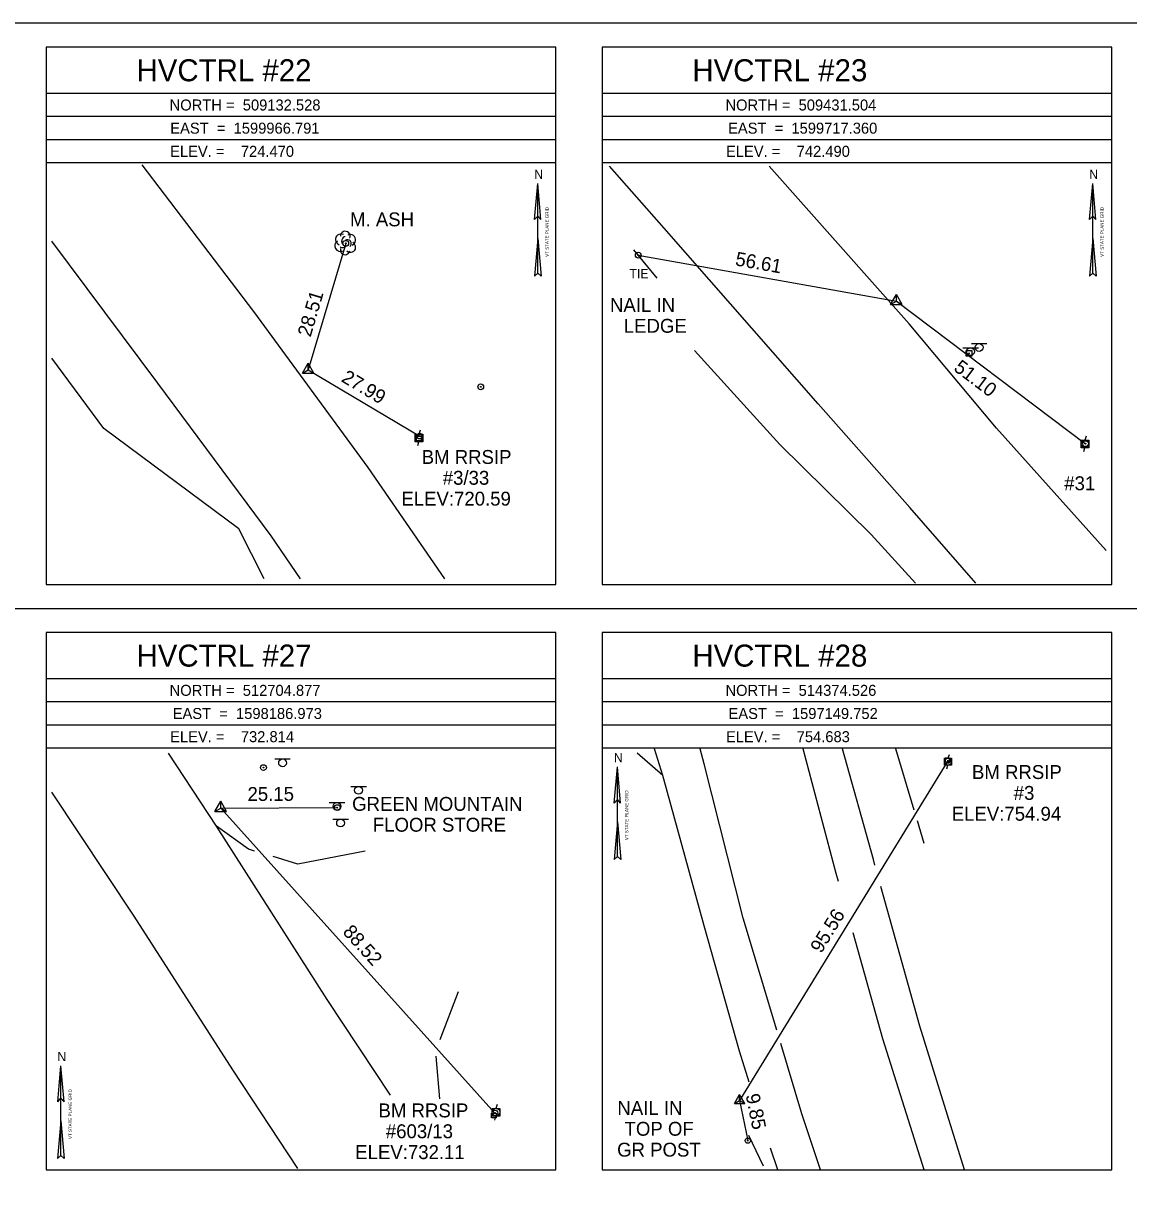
# Model space of a CAD drawing. Extents: x 1598730 to 1599370, y 501440 to 502728.
# Drawn here: x 1598999.5 to 1599238.2, y 501610.1 to 501860.2 of the extents above; entities that cross this region are included whole.
import ezdxf

# ---------------------------------------------------------------- set-up
doc = ezdxf.new("R2010")
doc.units = 0
for name, color, linetype in [('C_A', 7, 'Continuous'), ('C_C', 7, 'Continuous'), ('CBP', 7, 'Continuous'), ('CPBM', 7, 'Continuous'), ('CPSM', 7, 'Continuous'), ('Default', 7, 'Continuous'), ('L_C', 7, 'Continuous'), ('LARO', 7, 'Continuous'), ('LAWA', 7, 'Continuous'), ('LFNC', 7, 'Continuous'), ('LPST', 7, 'Continuous'), ('LTD', 7, 'Continuous'), ('NBL1', 7, 'Continuous'), ('NBL2', 7, 'Continuous'), ('NNA_P', 7, 'Continuous'), ('PET', 7, 'Continuous'), ('PSP', 7, 'Continuous'), ('RGR', 7, 'Continuous'), ('S_C', 7, 'Continuous'), ('SRM', 7, 'Continuous'), ('SSGN', 7, 'Continuous'), ('U_C', 7, 'Continuous'), ('UP', 7, 'Continuous'), ('UPGW', 7, 'Continuous')]:
    doc.layers.add(name, color=color, linetype=linetype)

msp = doc.modelspace()

# ---------------------------------------------------------------- linework, layer by layer
at = {"layer": 'CBP'}
for centre, radius in [((1599069.18, 501812.68), 0.625), ((1599069.18, 501812.68), 0.0833), ((1599132.32, 501810.14), 0.625), ((1599132.32, 501810.14), 0.0833), ((1599085.15, 501771.09), 0.625), ((1599085.15, 501771.09), 0.0833), ((1599228.87, 501769.44), 0.625), ((1599228.87, 501769.44), 0.0833), ((1599199.19, 501701.02), 0.562), ((1599199.19, 501701.02), 0.075), ((1599067.35, 501690.89), 0.625), ((1599067.35, 501690.89), 0.0833), ((1599101.38, 501624.98), 0.625), ((1599101.38, 501624.98), 0.0833), ((1599155.96, 501619.01), 0.562), ((1599155.96, 501619.01), 0.075)]:
    msp.add_circle(centre, radius, dxfattribs=at)
at = {"layer": 'CPBM'}
for p, q in [((1599084.43, 501770.06), (1599084.43, 501771.06)), ((1599084.43, 501771.06), (1599085.43, 501771.06)), ((1599085.43, 501770.06), (1599084.43, 501770.06)), ((1599084.93, 501770.56), (1599084.93, 501770.56)), ((1599084.93, 501770.56), (1599084.93, 501770.56)), ((1599085.43, 501771.06), (1599085.43, 501770.06)), ((1599198.55, 501700.72), (1599198.55, 501701.62)), ((1599198.55, 501701.62), (1599199.45, 501701.62)), ((1599199.45, 501700.72), (1599198.55, 501700.72)), ((1599199, 501701.17), (1599199, 501701.17)), ((1599199, 501701.17), (1599199, 501701.17)), ((1599199.45, 501701.62), (1599199.45, 501700.72)), ((1599100.64, 501623.96), (1599100.64, 501624.96)), ((1599100.64, 501624.96), (1599101.64, 501624.96)), ((1599101.64, 501624.96), (1599101.64, 501623.96)), ((1599101.64, 501623.96), (1599100.64, 501623.96)), ((1599101.15, 501624.46), (1599101.15, 501624.46)), ((1599101.15, 501624.46), (1599101.15, 501624.46))]:
    msp.add_line(p, q, dxfattribs=at)
at = {"layer": 'CPSM'}
for p, q in [((1599186.8, 501799.47), (1599188.05, 501801.64)), ((1599186.8, 501799.47), (1599188.05, 501800.19)), ((1599189.3, 501799.47), (1599188.05, 501801.64)), ((1599188.05, 501800.19), (1599188.05, 501801.64)), ((1599188.05, 501800.19), (1599188.05, 501800.19)), ((1599188.05, 501800.19), (1599189.3, 501799.47)), ((1599186.8, 501799.47), (1599189.3, 501799.47)), ((1599059.82, 501784.64), (1599061.07, 501786.8)), ((1599059.82, 501784.64), (1599061.07, 501785.36)), ((1599062.32, 501784.64), (1599061.07, 501786.8)), ((1599061.07, 501785.36), (1599061.07, 501786.8)), ((1599061.07, 501785.36), (1599061.07, 501785.36)), ((1599061.07, 501785.36), (1599062.32, 501784.64)), ((1599059.82, 501784.64), (1599062.32, 501784.64)), ((1599040.94, 501690.09), (1599042.19, 501692.26)), ((1599043.44, 501690.09), (1599042.19, 501692.26)), ((1599042.19, 501690.81), (1599042.19, 501692.26)), ((1599040.94, 501690.09), (1599042.19, 501690.81)), ((1599040.94, 501690.09), (1599043.44, 501690.09)), ((1599042.19, 501690.81), (1599042.19, 501690.81)), ((1599042.19, 501690.81), (1599043.44, 501690.09)), ((1599153.08, 501627.05), (1599154.2, 501629)), ((1599153.08, 501627.05), (1599154.21, 501627.7)), ((1599155.33, 501627.05), (1599154.2, 501629)), ((1599154.21, 501627.7), (1599154.2, 501629)), ((1599154.21, 501627.7), (1599154.21, 501627.7)), ((1599154.21, 501627.7), (1599155.33, 501627.05)), ((1599153.08, 501627.05), (1599155.33, 501627.05))]:
    msp.add_line(p, q, dxfattribs=at)
at = {"layer": 'Default'}
for p, q in [((1599069.18, 501812.68), (1599061.07, 501785.36)), ((1599132.32, 501810.14), (1599188.05, 501800.19)), ((1599188.05, 501800.19), (1599228.87, 501769.44)), ((1599061.07, 501785.36), (1599085.15, 501771.09)), ((1599199.19, 501701.02), (1599154.21, 501627.7)), ((1599042.19, 501690.81), (1599067.35, 501690.89)), ((1599101.38, 501624.98), (1599042.19, 501690.81)), ((1599154.21, 501627.7), (1599155.96, 501619.01))]:
    msp.add_line(p, q, dxfattribs=at)
at = {"layer": 'LARO'}
msp.add_lwpolyline([(1599136.42, 501805.14), (1599131.36, 501811.29)], dxfattribs=at)
at = {"layer": 'LAWA'}
for points in [[(1599051.53, 501740.25), (1599046.12, 501751.05), (1599016.95, 501772.73), (1599005.75, 501787.89)], [(1599192.15, 501739.35), (1599182.61, 501749.84), (1599162.87, 501769.29), (1599144.5, 501789.54)]]:
    msp.add_lwpolyline(points, dxfattribs=at)
at = {"layer": 'LFNC'}
for points in [[(1599191.9, 501690.35), (1599187.9, 501703.59)], [(1599194.08, 501683.14), (1599192.59, 501688.06)]]:
    msp.add_lwpolyline(points, dxfattribs=at)
at = {"layer": 'LPST'}
for radius in [0.625, 0.0833]:
    msp.add_circle((1599051.41, 501699.53), radius, dxfattribs=at)
at = {"layer": 'LTD'}
msp.add_line((1599069.04, 501812.82), (1599069.04, 501812.82), dxfattribs=at)
msp.add_line((1599069.04, 501812.82), (1599069.04, 501812.82), dxfattribs=at)
msp.add_arc((1599069.08, 501814.25), 1.05, 335.5272, 180.9563, dxfattribs=at)
for centre, major_axis, ratio, start_param, end_param in [((1599068.24, 501813.48), (1.21, -0.51), 0.895232, 1.570796, 4.712389), ((1599070.08, 501813.4), (-1.14, -0.48), 0.949671, 1.570796, 4.712389), ((1599067.95, 501812.11), (0.58, -1.04), 0.959034, 3.141593, 6.283185), ((1599068.83, 501813.28), (-0.208, -0.792), 0.645439, 3.141593, 6.283185), ((1599069.54, 501812.65), (-0.5, 0.667), 0.989748, 3.141593, 6.283185), ((1599070.04, 501811.98), (-1.09, 0.79), 0.841452, 1.570796, 4.712389), ((1599069.04, 501811.32), (0.26, 1.06), 0.942809, 1.570796, 4.712389), ((1599068.58, 501812.07), (-0.625, -0.083), 0.423636, 0, 3.141593)]:
    msp.add_ellipse(centre, major_axis=major_axis, ratio=ratio, start_param=start_param, end_param=end_param, dxfattribs=at)
at = {"layer": 'NBL1'}
msp.add_lwpolyline([(1598729.53, 501440.21), (1599369.53, 501440.21), (1599369.53, 501860.21), (1598729.53, 501860.21)], close=True, dxfattribs=at)
at = {"layer": 'NBL2'}
for p, q in [((1599114.53, 501845.04), (1599004.53, 501845.04)), ((1599234.53, 501845.04), (1599124.53, 501845.04)), ((1599114.53, 501840.04), (1599004.53, 501840.04)), ((1599234.53, 501840.04), (1599124.53, 501840.04)), ((1599114.53, 501835.04), (1599004.53, 501835.04)), ((1599234.53, 501835.04), (1599124.53, 501835.04)), ((1599114.53, 501830.04), (1599004.53, 501830.04)), ((1599234.53, 501830.04), (1599124.53, 501830.04)), ((1598729.53, 501733.88), (1599369.53, 501733.88)), ((1599114.53, 501718.71), (1599004.53, 501718.71)), ((1599234.53, 501718.71), (1599124.53, 501718.71)), ((1599114.53, 501713.71), (1599004.53, 501713.71)), ((1599234.53, 501713.71), (1599124.53, 501713.71)), ((1599114.53, 501708.71), (1599004.53, 501708.71)), ((1599234.53, 501708.71), (1599124.53, 501708.71)), ((1599114.53, 501703.71), (1599004.53, 501703.71)), ((1599234.53, 501703.71), (1599124.53, 501703.71))]:
    msp.add_line(p, q, dxfattribs=at)
for points in [[(1599004.53, 501739.04), (1599114.53, 501739.04), (1599114.53, 501855.04), (1599004.53, 501855.04)], [(1599124.53, 501739.04), (1599234.53, 501739.04), (1599234.53, 501855.04), (1599124.53, 501855.04)], [(1599004.53, 501612.71), (1599114.53, 501612.71), (1599114.53, 501728.71), (1599004.53, 501728.71)], [(1599124.53, 501612.71), (1599234.53, 501612.71), (1599234.53, 501728.71), (1599124.53, 501728.71)]]:
    msp.add_lwpolyline(points, close=True, dxfattribs=at)
at = {"layer": 'NNA_P'}
for p, q in [((1599109.93, 501817.8), (1599110.63, 501825.6)), ((1599110.63, 501806.22), (1599110.63, 501825.6)), ((1599111.32, 501817.8), (1599110.63, 501825.6)), ((1599229.75, 501817.8), (1599230.45, 501825.6)), ((1599230.45, 501806.22), (1599230.45, 501825.6)), ((1599231.14, 501817.8), (1599230.45, 501825.6)), ((1599109.93, 501817.8), (1599110.63, 501818.57)), ((1599111.32, 501817.8), (1599110.63, 501818.57)), ((1599229.75, 501817.8), (1599230.45, 501818.57)), ((1599231.14, 501817.8), (1599230.45, 501818.57)), ((1599110.63, 501813.75), (1599109.91, 501805.58)), ((1599110.63, 501813.75), (1599111.35, 501805.58)), ((1599230.45, 501813.75), (1599229.73, 501805.58)), ((1599230.45, 501813.75), (1599231.17, 501805.58)), ((1599110.63, 501806.22), (1599109.91, 501805.58)), ((1599110.63, 501806.22), (1599111.35, 501805.58)), ((1599230.45, 501806.22), (1599229.73, 501805.58)), ((1599230.45, 501806.22), (1599231.17, 501805.58)), ((1599127.12, 501691.89), (1599127.82, 501699.68)), ((1599127.82, 501680.31), (1599127.82, 501699.68)), ((1599128.51, 501691.89), (1599127.82, 501699.68)), ((1599127.12, 501691.89), (1599127.82, 501692.66)), ((1599128.51, 501691.89), (1599127.82, 501692.66)), ((1599127.82, 501687.84), (1599127.1, 501679.67)), ((1599127.82, 501687.84), (1599128.54, 501679.67)), ((1599127.82, 501680.31), (1599127.1, 501679.67)), ((1599127.82, 501680.31), (1599128.54, 501679.67)), ((1599006.99, 501627.38), (1599007.69, 501635.17)), ((1599007.69, 501615.8), (1599007.69, 501635.17)), ((1599008.38, 501627.38), (1599007.69, 501635.17)), ((1599006.99, 501627.38), (1599007.69, 501628.15)), ((1599008.38, 501627.38), (1599007.69, 501628.15)), ((1599007.69, 501623.32), (1599006.97, 501615.16)), ((1599007.69, 501623.32), (1599008.41, 501615.16)), ((1599007.69, 501615.8), (1599006.97, 501615.16)), ((1599007.69, 501615.8), (1599008.41, 501615.16))]:
    msp.add_line(p, q, dxfattribs=at)
at = {"layer": 'PET'}
for points in [[(1599090.58, 501740.25), (1599074, 501764.28), (1599049.3, 501798), (1599025.24, 501829.62)], [(1599205.19, 501739.35), (1599190.92, 501755.67), (1599171.18, 501778.03), (1599137.92, 501815.97), (1599126.15, 501829.31)], [(1599233.34, 501746.41), (1599209.63, 501772.82), (1599190.83, 501795.28), (1599160.62, 501829.31)], [(1599059.39, 501740.25), (1599053.08, 501749.55), (1599028.64, 501782.5), (1599005.75, 501813.19)], [(1599078.83, 501628.86), (1599065.14, 501649.45), (1599041.25, 501686.87), (1599030.93, 501702.68)], [(1599137.65, 501697.84), (1599132.07, 501702.67)], [(1599162.24, 501642.84), (1599154.95, 501667.05), (1599146.56, 501700.33), (1599145.72, 501703.59)], [(1599175.57, 501674.92), (1599175.08, 501676.69), (1599167.94, 501703.59)], [(1599058.82, 501613.01), (1599044.79, 501634.28), (1599023.51, 501667.44), (1599005.75, 501694.24)], [(1599049.51, 501681.51), (1599048.15, 501681.92), (1599041.25, 501686.87)], [(1599073.36, 501681.46), (1599058.8, 501678.69), (1599053.48, 501680.31)], [(1599194.03, 501612.71), (1599185.13, 501641.01), (1599178.69, 501663.86)], [(1599093.41, 501651.16), (1599089.46, 501640.74)], [(1599171.67, 501612.71), (1599167.66, 501624.82), (1599163.11, 501639.95)], [(1599088.65, 501637.23), (1599089.38, 501628.06)]]:
    msp.add_lwpolyline(points, dxfattribs=at)
at = {"layer": 'PSP'}
for points in [[(1599156.3, 501631.65), (1599154.19, 501638.32), (1599146.58, 501665.35), (1599137.65, 501697.84), (1599135.82, 501703.59)], [(1599183.42, 501678.46), (1599183.08, 501679.68), (1599176.43, 501703.59)], [(1599202.79, 501612.71), (1599193.09, 501643.73), (1599190.65, 501652.49), (1599184.69, 501673.9)], [(1599162.43, 501612.71), (1599160.86, 501617.42)]]:
    msp.add_lwpolyline(points, dxfattribs=at)
at = {"layer": 'RGR'}
msp.add_lwpolyline([(1599159.34, 501613.54), (1599156.19, 501620.09)], dxfattribs=at)
at = {"layer": 'SRM'}
msp.add_lwpolyline([(1599203.1, 501789.58), (1599204.35, 501789.58), (1599204.35, 501788.33), (1599203.1, 501788.33)], close=True, dxfattribs=at)
msp.add_circle((1599203.73, 501788.96), 0.0833, dxfattribs=at)
at = {"layer": 'SSGN'}
for p, q in [((1599202.41, 501790.16), (1599205.75, 501790.16)), ((1599204.27, 501791.04), (1599207.6, 501791.04)), ((1599205.92, 501790.21), (1599205.92, 501790.21)), ((1599204.06, 501789.33), (1599204.06, 501789.33)), ((1599053.88, 501701.39), (1599057.21, 501701.39)), ((1599055.53, 501700.56), (1599055.53, 501700.56)), ((1599070.29, 501695.46), (1599073.62, 501695.46)), ((1599071.93, 501694.63), (1599071.93, 501694.63)), ((1599065.62, 501692.01), (1599068.96, 501692.01)), ((1599067.27, 501691.18), (1599067.27, 501691.18)), ((1599066.4, 501688.4), (1599069.74, 501688.4)), ((1599068.05, 501687.57), (1599068.05, 501687.57))]:
    msp.add_line(p, q, dxfattribs=at)
for centre in [(1599204.06, 501789.33), (1599205.92, 501790.21), (1599055.53, 501700.56), (1599071.93, 501694.63), (1599067.27, 501691.18), (1599068.05, 501687.57)]:
    msp.add_circle(centre, 0.833, dxfattribs=at)
at = {"layer": 'UP'}
for p, q in [((1599085.24, 501772.35), (1599084.99, 501771.52)), ((1599084.16, 501769.85), (1599084.16, 501771.52)), ((1599084.16, 501771.52), (1599085.83, 501771.52)), ((1599085.83, 501769.85), (1599084.16, 501769.85)), ((1599084.74, 501769.02), (1599084.99, 501769.85)), ((1599084.99, 501770.68), (1599084.99, 501770.68)), ((1599085.83, 501771.52), (1599085.83, 501769.85)), ((1599227.92, 501768.57), (1599227.92, 501770.24)), ((1599227.92, 501770.24), (1599229.58, 501770.24)), ((1599229, 501771.07), (1599228.75, 501770.24)), ((1599229.58, 501770.24), (1599229.58, 501768.57)), ((1599229.58, 501768.57), (1599227.92, 501768.57)), ((1599228.5, 501767.74), (1599228.75, 501768.57)), ((1599228.75, 501769.4), (1599228.75, 501769.4)), ((1599199.42, 501702.3), (1599199.19, 501701.55)), ((1599198.44, 501700.05), (1599198.44, 501701.55)), ((1599198.44, 501701.55), (1599199.94, 501701.55)), ((1599199.94, 501700.05), (1599198.44, 501700.05)), ((1599198.97, 501699.3), (1599199.19, 501700.05)), ((1599199.19, 501700.8), (1599199.19, 501700.8)), ((1599199.94, 501701.55), (1599199.94, 501700.05)), ((1599100.78, 501624.3), (1599100.78, 501625.97)), ((1599100.78, 501625.97), (1599102.45, 501625.97)), ((1599101.86, 501626.8), (1599101.61, 501625.97)), ((1599101.61, 501625.14), (1599101.61, 501625.14)), ((1599102.45, 501625.97), (1599102.45, 501624.3)), ((1599102.45, 501624.3), (1599100.78, 501624.3)), ((1599101.36, 501623.47), (1599101.61, 501624.3))]:
    msp.add_line(p, q, dxfattribs=at)
for centre, radius in [((1599084.99, 501770.68), 0.833), ((1599228.75, 501769.4), 0.833), ((1599199.19, 501700.8), 0.75), ((1599101.61, 501625.14), 0.833)]:
    msp.add_circle(centre, radius, dxfattribs=at)
at = {"layer": 'UPGW'}
for radius in [0.625, 0.0833]:
    msp.add_circle((1599098.32, 501781.72), radius, dxfattribs=at)

# ---------------------------------------------------------------- texts
at = {"layer": 'C_A'}
msp.add_text('TIE', height=2, dxfattribs=at).set_placement((1599130.4, 501805.14))
at = {"layer": 'C_C'}
for s, p in [('NAIL IN', (1599126.22, 501797.89)), ('LEDGE', (1599129.2, 501793.39)), ('BM RRSIP', (1599085.57, 501765.08)), ('#3/33', (1599090.12, 501760.58)), ('ELEV:720.59', (1599081.18, 501756.08)), ('NAIL IN', (1599127.82, 501624.57)), ('TOP OF', (1599129.37, 501620.07)), ('GR POST', (1599127.76, 501615.57))]:
    msp.add_text(s, height=3, dxfattribs=at).set_placement(p)
at = {"layer": 'Default'}
for s, rotation, p in [('56.61', 349.8841, (1599153.12, 501807.95)), ('28.51', 73.4616, (1599061.57, 501792.31)), ('51.10', 323.0005, (1599200.23, 501785.39)), ('27.99', 329.3655, (1599068.02, 501782.98)), ('25.15', 0.1826, (1599047.97, 501692.33)), ('95.56', 58.4658, (1599171.82, 501659.28)), ('88.52', 311.9517, (1599068.36, 501663.95)), ('9.85', 281.4063, (1599155.5, 501628.85))]:
    msp.add_text(s, height=3, rotation=rotation, dxfattribs=at).set_placement(p)
at = {"layer": 'L_C'}
msp.add_text('M. ASH', height=3, dxfattribs=at).set_placement((1599070.1, 501816.36))
at = {"layer": 'NBL2'}
for s, height, p in [('     HVCTRL #22    ', 4.75, (1599015.18, 501847.67)), ('     HVCTRL #23    ', 4.75, (1599135.18, 501847.67)), ('NORTH =  509132.528 ', 2.375, (1599031.15, 501841.36)), ('NORTH =  509431.504 ', 2.375, (1599151.15, 501841.36)), ('EAST  =  1599966.791', 2.375, (1599031.29, 501836.36)), ('EAST  =  1599717.360', 2.375, (1599151.71, 501836.36)), ('ELEV. =    724.470  ', 2.375, (1599031.26, 501831.36)), ('ELEV. =    742.490  ', 2.375, (1599151.26, 501831.36)), ('     HVCTRL #27    ', 4.75, (1599015.18, 501721.33)), ('     HVCTRL #28    ', 4.75, (1599135.18, 501721.33)), ('NORTH =  512704.877 ', 2.375, (1599031.15, 501715.02)), ('NORTH =  514374.526 ', 2.375, (1599151.15, 501715.02)), ('EAST  =  1598186.973', 2.375, (1599031.81, 501710.02)), ('EAST  =  1597149.752', 2.375, (1599151.81, 501710.02)), ('ELEV. =    732.814  ', 2.375, (1599031.26, 501705.02)), ('ELEV. =    754.683  ', 2.375, (1599151.26, 501705.02))]:
    msp.add_text(s, height=height, dxfattribs=at).set_placement(p)
at = {"layer": 'NNA_P'}
for p in [(1599109.87, 501826.61), (1599229.69, 501826.61), (1599127.06, 501700.7), (1599006.92, 501636.18)]:
    msp.add_text('N', height=1.97, dxfattribs=at).set_placement(p)
for p in [(1599112.98, 501809.78), (1599232.8, 501809.78), (1599130.17, 501683.87), (1599010.04, 501619.36)]:
    msp.add_text('VT STATE PLANE GRID', height=0.7, rotation=90.0204, dxfattribs=at).set_placement(p)
at = {"layer": 'S_C'}
for s, p in [('GREEN MOUNTAIN', (1599070.55, 501690.2)), ('FLOOR STORE', (1599075.02, 501685.7))]:
    msp.add_text(s, height=3, dxfattribs=at).set_placement(p)
at = {"layer": 'U_C'}
for s, p in [('#31', (1599224.29, 501759.4)), ('BM RRSIP', (1599204.37, 501697.07)), ('#3', (1599213.38, 501692.57)), ('ELEV:754.94', (1599199.99, 501688.07)), ('BM RRSIP', (1599076.25, 501624.04)), ('#603/13', (1599077.83, 501619.54)), ('ELEV:732.11', (1599071.22, 501615.04))]:
    msp.add_text(s, height=3, dxfattribs=at).set_placement(p)

doc.saveas('drawing.dxf')
